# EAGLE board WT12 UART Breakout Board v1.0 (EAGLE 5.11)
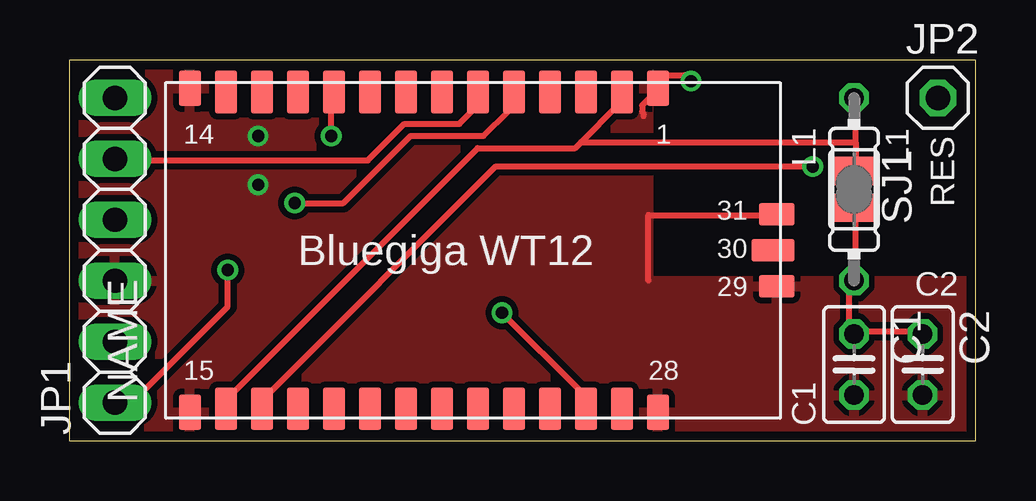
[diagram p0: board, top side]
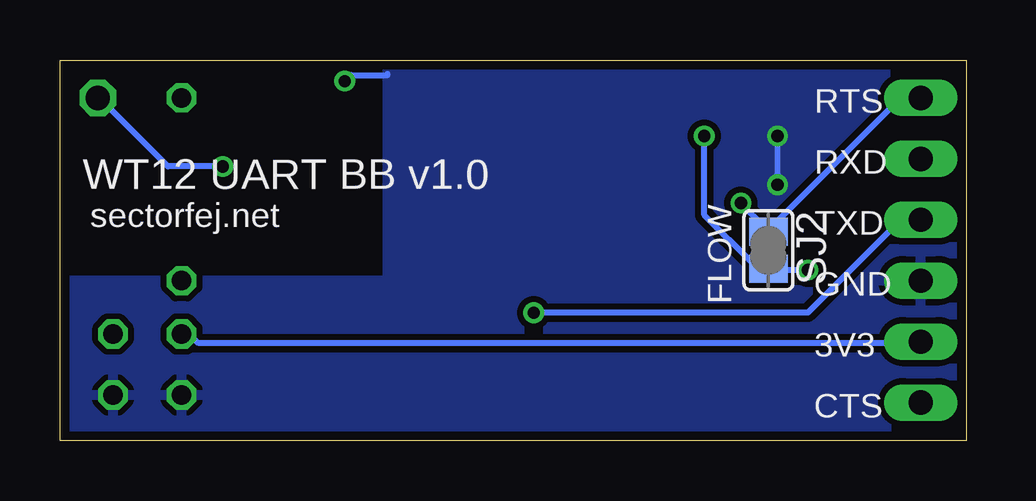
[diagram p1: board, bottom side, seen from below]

Size 37.77 x 15.87 mm. Coordinates in mm from the lower left corner, seen from the top.
Outline: 0,0 37.77,0 37.77,15.87 0,15.87 0,0
Copper layers (1*16): Top 0.0356mm / dielectric 1.5011mm / Bottom 0.0356mm
Design rules "LaenPCBOrder": minimum track width 6mil, minimum drill 13mil, track to track 6mil, track to pad 6mil, pad to pad 6mil, via to via 6mil, smd to smd 6mil, copper to edge 15mil, drill to drill 6mil, minimum pad ring 7mil, minimum via ring 7mil, stop-mask expansion 4mil, vias tented up to drill 0mil, thermal gap 10mil
Net classes: 0 default: width 0.254 mm, drill 0.508 mm, clearance 0.254 mm

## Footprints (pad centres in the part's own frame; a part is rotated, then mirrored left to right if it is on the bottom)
C025-025X050 = drill 0.813 octagon: 1 -1.27,0; 2 1.27,0
1X06 = drill 1.016 long: 1 -6.35,0; 2 -3.81,0; 3 -1.27,0; 4 1.27,0; 5 3.81,0; 6 6.35,0
1X01 = drill 1.016 octagon: 1 0,0
0204/7 = drill 0.813 octagon: 1 -3.81,0; 2 3.81,0
SJ = smd 1.168 x 1.6: 1 -0.762,0; 2 0.762,0
WT12 = smd 0.914 x 1.478: GND1 7.7,6.75; GND2 -11.8,6.75; GND3 -11.8,-6.75; GND4 7.7,-6.75 | smd 1.478 x 0.914: GND5 12.65,-1.5; GND6 12.65,1.5 | smd 0.914 x 1.778: MISO 0.2,-6.6; MOSI 1.7,-6.6; NC 6.2,-6.6; NCSB -2.8,-6.6; NCTS -5.8,6.6; NRTS 1.7,6.6; PCMC -8.8,6.6; PCMI -7.3,6.6; PCMO -1.3,6.6; PCMS -10.3,6.6; PIO2 4.7,6.6; PIO3 3.2,6.6; PIO4 -4.3,-6.6; PIO5 3.2,-6.6; PIO6 -7.3,-6.6; PIO7 -5.8,-6.6; RES -8.8,-6.6; RXD 0.2,6.6; SCLK -1.3,-6.6; TXD 4.7,-6.6; USB_D+ -2.8,6.6; USB_D- -4.3,6.6; VDD1 6.2,6.6; VDD2 -10.3,-6.6 | smd 1.778 x 0.914: RF 12.5,0

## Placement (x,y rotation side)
C1  100 nF  [C025-025X050]  32.7,3.17 270 top
C2  NP  [C025-025X050]  35.56,3.17 270 top
JP1  UART  [1X06]  1.91,7.94 90 top
JP2  RESET  [1X01]  36.2,14.29 0 top
L1  10 nH  [0204/7]  32.7,10.48 270 top
SJ1  PWR  [SJ]  32.7,10.48 270 top
SJ2  FLOW  [SJ]  8.26,7.94 270 bottom
U1  WT12  [WT12]  16.83,7.94 0 top

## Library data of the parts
C1 C2 L1 = resistor
JP1 JP2 = pinhead
SJ1 SJ2 = jumper
U1 = wt12

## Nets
3V3: C1.1 C2.1 JP1.2 L1.2 SJ1.2
GND: C1.2 C2.2 JP1.3 U1.GND1 U1.GND2 U1.GND3 U1.GND4 U1.GND5 U1.GND6
MISO: U1.MISO
MOSI: U1.MOSI
NC: U1.NC
NCSB: U1.NCSB
NCTS: JP1.1 SJ2.2 U1.NCTS
NRTS: JP1.6 SJ2.1 U1.NRTS
PCMC: U1.PCMC
PCMI: U1.PCMI
PCMO: U1.PCMO
PCMS: U1.PCMS
PIO2: U1.PIO2
PIO3: U1.PIO3
PIO4: U1.PIO4
PIO5: U1.PIO5
PIO6: U1.PIO6
PIO7: U1.PIO7
RES: JP2.1 U1.RES
RF: U1.RF
RXD: JP1.5 U1.RXD
SCLK: U1.SCLK
TXD: JP1.4 U1.TXD
USB_D+: U1.USB_D+
USB_D-: U1.USB_D-
VCC: L1.1 SJ1.1 U1.VDD1 U1.VDD2

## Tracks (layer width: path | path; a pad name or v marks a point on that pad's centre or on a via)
3V3
  Top 0.254: SJ1.2 32.77,9.65 32.77,6.86 L1.2 32.51,6.6 32.51,4.57 C1.1 32.77,4.57 35.56,4.57 C2.1
  Bottom 0.254: JP1.2 2.03,4.06 32,4.06 32.51,4.57 C1.1
GND  (via drill 0.51)
  Top 0.254: U1.GND6 29.46,9.4 24.13,9.4 24.13,6.67 | 23.94,13.53 23.88,13.72 23.88,13.97 24.38,14.48 U1.GND1 24.64,14.73 24.64,15.24 25.65,15.24 v25.91,14.99
  Bottom 0.254: v7.87,10.67 v7.87,12.7 | v25.91,14.99 25.65,15.24 24.13,15.24 24.13,15.28
  pour Bottom: 0,15.88 24.13,15.88 24.13,6.67 37.78,6.67 37.78,0 0,0
  pour Top: 0,15.88 24.13,15.88 24.13,6.67 37.78,6.67 37.78,0 0,0
NCTS  (via drill 0.51)
  Top 0.254: v6.6,7.11 6.6,5.59 2.79,1.78 2.03,1.78 JP1.1 | v10.92,12.7 10.92,14.48 U1.NCTS
  Bottom 0.254: v6.6,7.11 8.13,7.11 SJ2.2 8.38,7.37 8.89,7.37 10.92,9.4 v10.92,12.7
NRTS  (via drill 0.51)
  Top 0.254: v9.4,9.91 11.43,9.91 14.22,12.7 17.27,12.7 18.29,13.72 18.29,14.48 U1.NRTS
  Bottom 0.254: JP1.6 2.03,14.22 2.79,14.22 8.13,8.89 SJ2.1 8.38,8.89 v9.4,9.91
RES  (via drill 0.51)
  Top 0.254: v30.99,11.43 17.78,11.43 8.13,1.78 8.13,1.52 U1.RES
  Bottom 0.254: v30.99,11.43 33.27,11.43 36.07,14.22 JP2.1
RXD
  Top 0.254: U1.RXD 17.02,14.48 17.02,13.97 16.26,13.21 13.97,13.21 12.45,11.68 2.03,11.68 JP1.5
TXD  (via drill 0.51)
  Top 0.254: v18.03,5.33 21.34,2.03 21.34,1.52 U1.TXD
  Bottom 0.254: v18.03,5.33 6.6,5.33 2.79,9.14 2.03,9.14 JP1.4
VCC
  Top 0.254: 32.77,12.45 32.77,14.22 L1.1 | 32.77,12.45 32.77,11.43 SJ1.1 | 21.34,12.45 22.86,13.97 22.86,14.48 U1.VDD1 | 21.34,12.45 21.08,12.19 17.02,12.19 6.6,1.78 6.6,1.52 U1.VDD2 | 21.34,12.45 32.77,12.45

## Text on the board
tPlace: RES | 14 | 1 | L1 | 31 | 30 | Bluegiga WT12 | 29 | C2 | 15 | 28 | C1
bPlace: RTS | RXD | FLOW | WT12 UART BB v1.0 | TXD | sectorfej.net | GND | 3V3 | CTS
